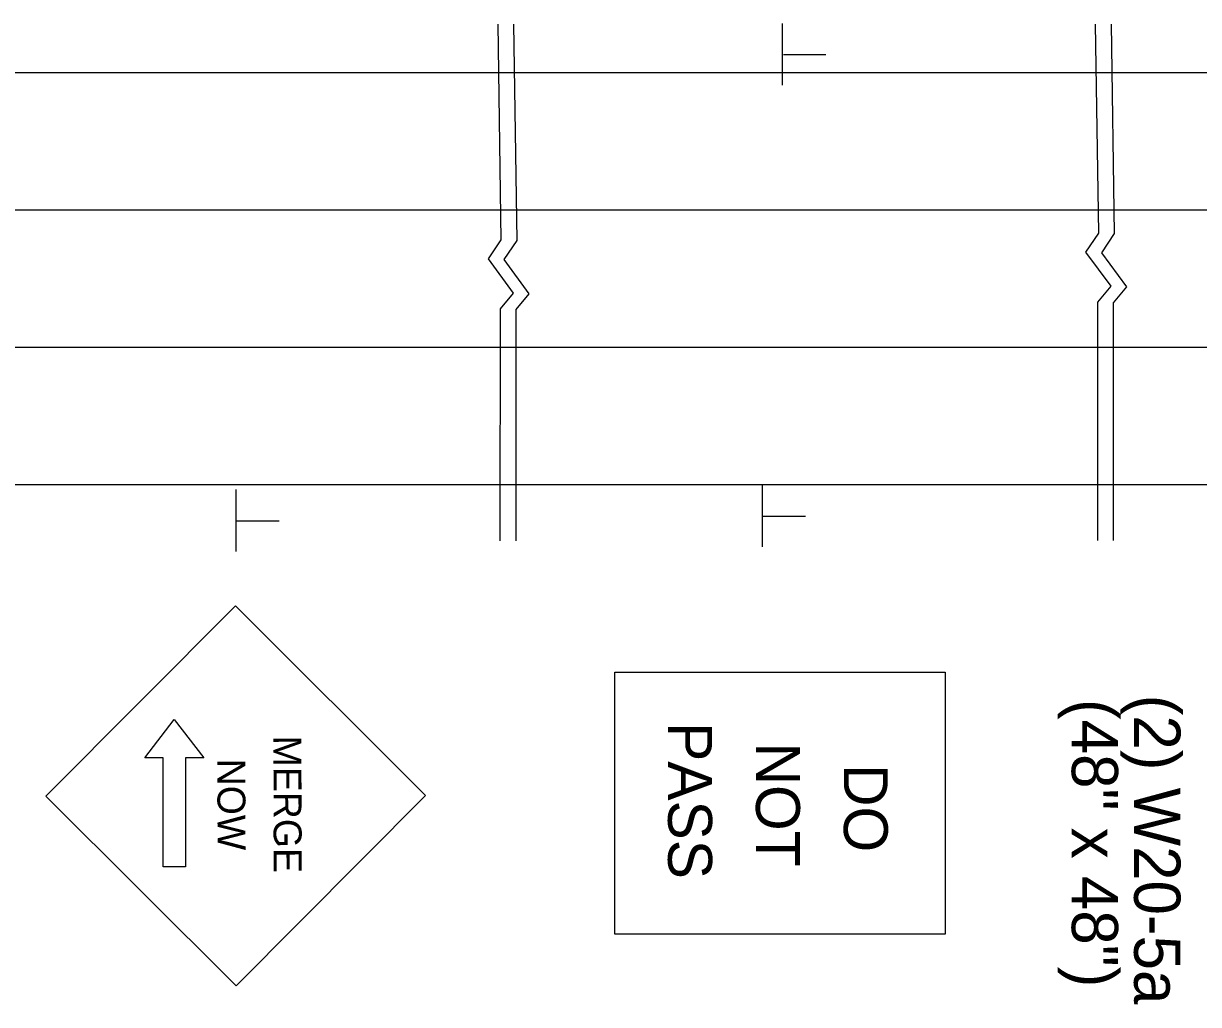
# Model space of a CAD drawing. Extents: x -100 to 745, y -1581 to -107.
# Drawn here: x 610.84 to 625.72, y -524.27 to -511.85 of the extents above; entities that cross this region are included whole.
import ezdxf

# ---------------------------------------------------------------- set-up
doc = ezdxf.new("R2010")
doc.units = 0
doc.layers.add('Default', color=7, linetype='Continuous')

msp = doc.modelspace()

# ---------------------------------------------------------------- linework, layer by layer
at = {"layer": 'Default'}
for p, q in [((620.451, -512.63), (620.451, -511.848)), ((620.463, -512.241), (620.997, -512.241)), ((609.446, -512.467), (616.347, -512.467)), ((616.347, -512.467), (623.741, -512.467)), ((623.741, -512.467), (629.938, -512.467)), ((609.446, -514.205), (616.347, -514.205)), ((616.347, -514.205), (623.786, -514.205)), ((623.786, -514.205), (629.904, -514.205)), ((609.446, -515.944), (616.347, -515.944)), ((616.347, -515.944), (623.786, -515.944)), ((623.786, -515.944), (629.904, -515.944)), ((609.446, -517.682), (616.347, -517.682)), ((613.527, -518.531), (613.527, -517.748)), ((616.347, -517.682), (623.832, -517.682)), ((620.194, -518.474), (620.194, -517.692)), ((623.832, -517.682), (629.87, -517.682)), ((620.205, -518.085), (620.739, -518.085)), ((613.538, -518.142), (614.072, -518.142)), ((611.12, -521.629), (613.521, -519.219)), ((615.929, -521.621), (613.521, -519.219)), ((612.37, -521.144), (612.745, -520.657)), ((612.745, -520.657), (613.12, -521.144)), ((612.604, -521.144), (612.37, -521.144)), ((612.604, -522.523), (612.604, -521.144)), ((612.886, -521.144), (612.886, -522.523)), ((613.12, -521.144), (612.886, -521.144)), ((613.53, -524.03), (611.12, -521.629)), ((613.53, -524.03), (615.929, -521.621)), ((612.886, -522.523), (612.604, -522.523))]:
    msp.add_line(p, q, dxfattribs=at)
for points in [[(616.842, -511.855), (616.883, -514.587), (616.721, -514.828), (617.038, -515.261), (616.871, -515.461), (616.87, -518.398)], [(617.042, -511.855), (617.083, -514.595), (616.921, -514.836), (617.237, -515.269), (617.071, -515.469), (617.07, -518.398)], [(624.411, -511.855), (624.452, -514.5), (624.289, -514.742), (624.606, -515.174), (624.439, -515.374), (624.438, -518.394)], [(624.611, -511.855), (624.651, -514.508), (624.489, -514.75), (624.805, -515.183), (624.639, -515.383), (624.638, -518.394)]]:
    msp.add_lwpolyline(points, dxfattribs=at)
msp.add_lwpolyline([(622.508, -523.376), (618.326, -523.376), (618.326, -520.058), (622.508, -520.058)], close=True, dxfattribs=at)

# ---------------------------------------------------------------- texts
for s, height, rotation, p in [('(48" x 48")', 0.5862, 270, (624.113, -520.399)), ('(2) W20-5a', 0.5862, 270, (624.903, -520.345)), ('PASS', 0.5566, 270, (619, -520.691)), ('MERGE', 0.3544, 270.1004, (614.001, -520.863)), ('NOT', 0.5566, 270, (620.113, -520.95)), ('NOW', 0.3543, 270.1003, (613.291, -521.155)), ('DO', 0.5566, 270, (621.226, -521.222))]:
    msp.add_text(s, height=height, rotation=rotation, dxfattribs=at).set_placement(p)

doc.saveas('drawing.dxf')
